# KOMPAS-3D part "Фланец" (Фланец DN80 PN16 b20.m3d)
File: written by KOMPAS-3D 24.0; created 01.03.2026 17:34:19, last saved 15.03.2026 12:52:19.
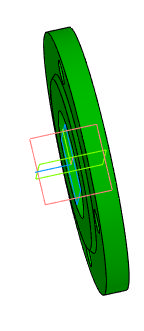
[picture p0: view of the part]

Document properties: Автор: R2D2; Полное имя файла: E:\Работа\Зайцев\GVWR2626M-2W-F-S Задвижка клиновая с выдвижным штоком DN.ru Ду50-300 Ру16\DN80\исходные материалы\Фланец DN80 PN16 b20.m3d

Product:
- Part/product: Фланец
    Масса: 3.375667
    additional columns: Типовые

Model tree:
1. Эскиз:2
2. Элемент вращения:1
     Угол 1 = 360
3. Эскиз:3  (with: Грань.Элемент вращения:1)
4. Элемент выдавливания:2
     Расстояние 2 = 17
5. Массив по концентрической сетке:1  (with: Элемент выдавливания:2, Эскиз:3, Грань.Элемент вращения:1)  (4 pattern instances)
     Шаг 2 = 360
6. Эскиз:4  (with: Грань.Элемент вращения:1)
7. Элемент выдавливания:3
     Расстояние 2 = 2.5

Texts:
  Линейный размер с обрывом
